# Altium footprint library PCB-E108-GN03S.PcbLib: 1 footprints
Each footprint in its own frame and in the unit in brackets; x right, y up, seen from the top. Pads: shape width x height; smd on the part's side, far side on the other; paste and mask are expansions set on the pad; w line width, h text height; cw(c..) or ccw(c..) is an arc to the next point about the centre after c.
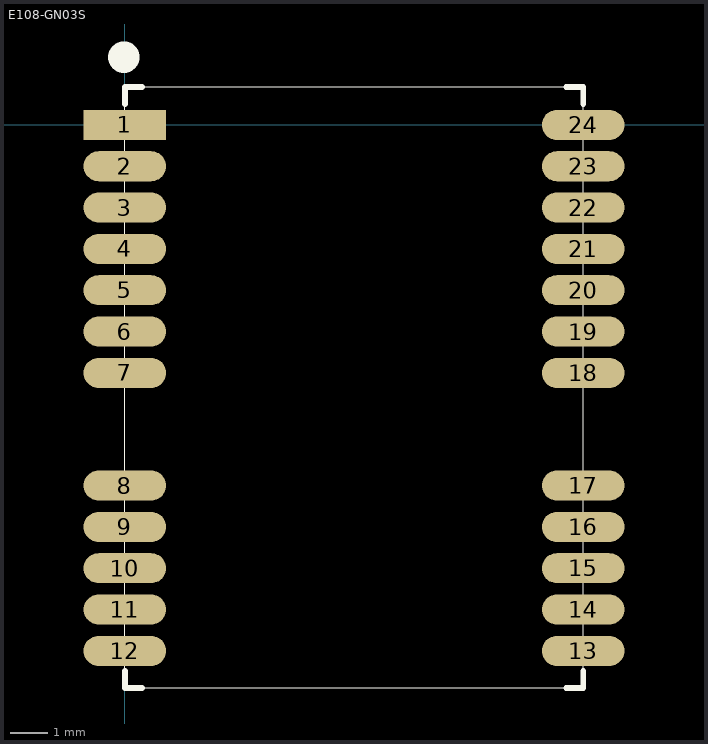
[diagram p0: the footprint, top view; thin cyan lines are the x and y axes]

## E108-GN03S [mm]
height 2.13
pads (24):
  rect 2.2x0.8 smd mask+0.025: 1(0,0)
  oval 2.2x0.8 smd mask+0.025: 2(0,-1.1) 3(0,-2.2) 4(0,-3.3) 5(0,-4.4) 6(0,-5.5) 7(0,-6.6) 8(0,-9.6) 9(0,-10.7) 10(0,-11.8) 11(0,-12.9) 12(0,-14) 13(12.2,-14) 14(12.2,-12.9) 15(12.2,-11.8) 16(12.2,-10.7) 17(12.2,-9.6) 18(12.2,-6.6) 19(12.2,-5.5) 20(12.2,-4.4) 21(12.2,-3.3) 22(12.2,-2.2) 23(12.2,-1.1) 24(12.2,0)
Top Overlay:
  circle w0.762: c-0.025,1.803 r0.036
  lines w0.025: 0.003,-14.988 12.203,-14.988 12.203,1.012 0.003,1.012 0.003,-14.988
  lines w0.152: 0.003,-14.534 0.003,-14.988 0.457,-14.988 ; 0.003,0.558 0.003,1.012 0.457,1.012 ; 11.749,-14.988 12.203,-14.988 12.203,-14.534 ; 11.749,1.012 12.203,1.012 12.203,0.558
